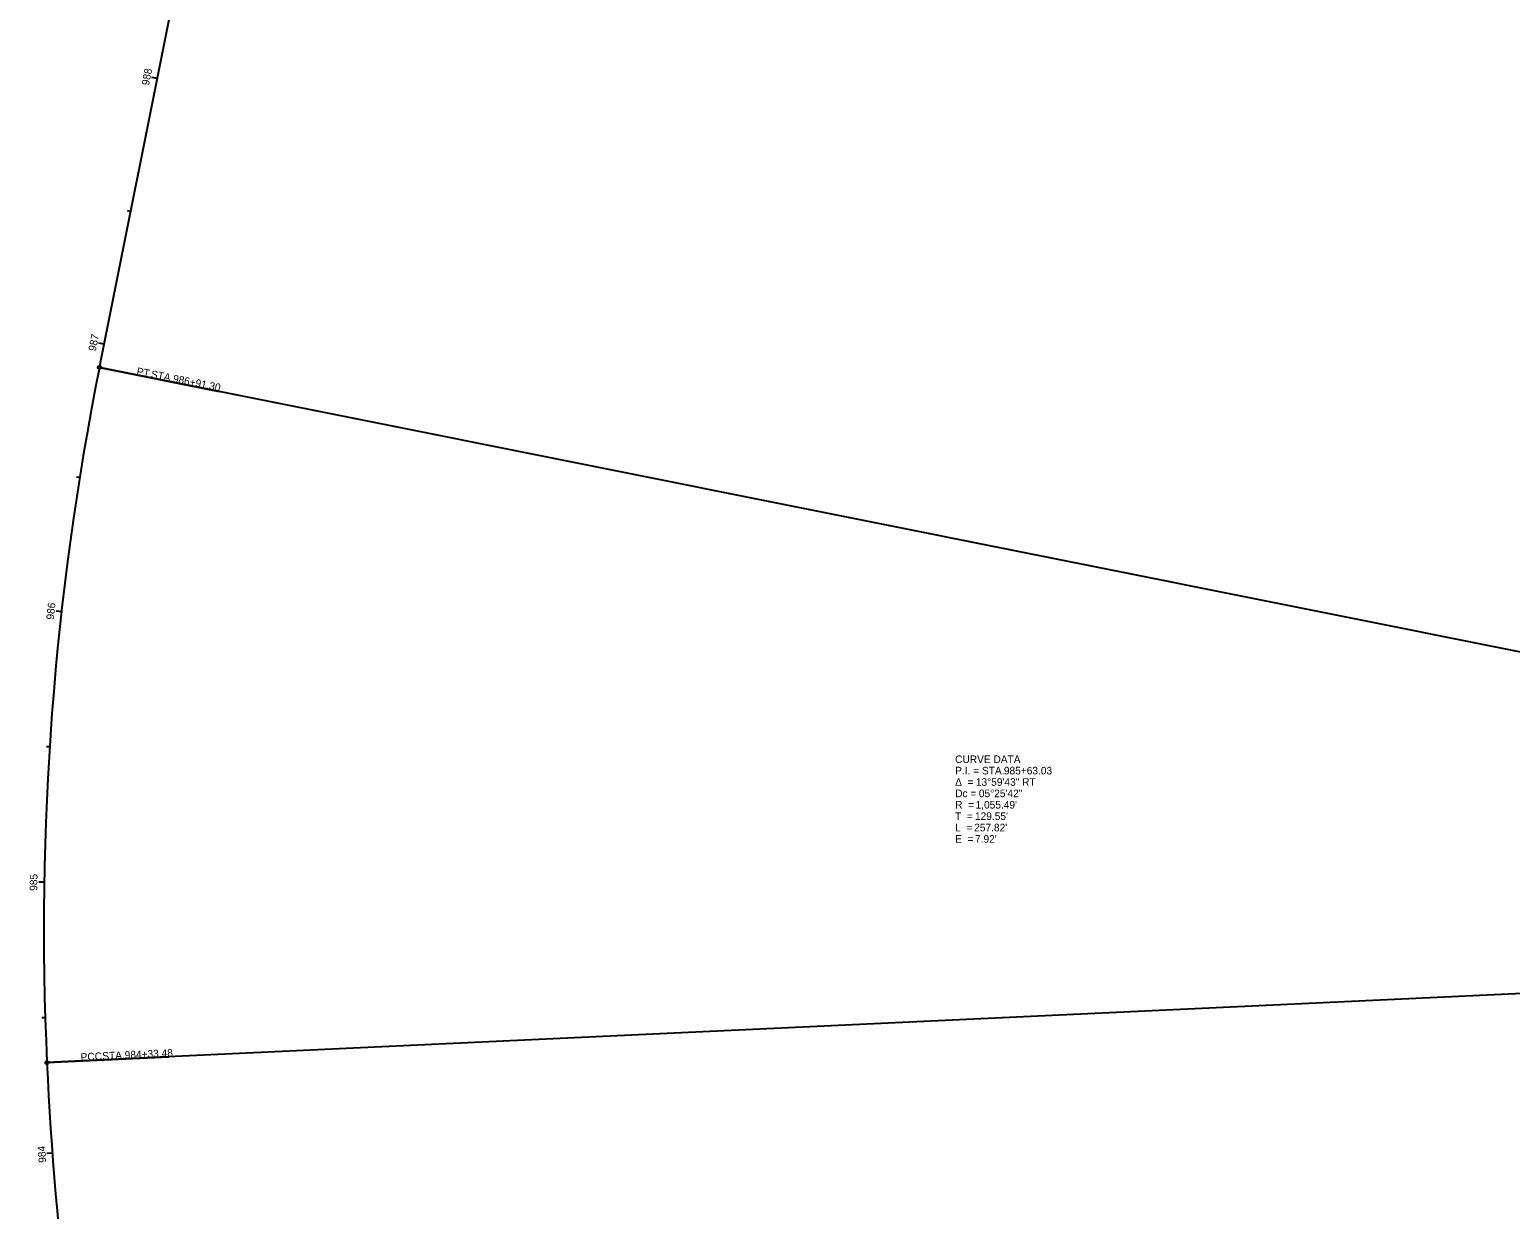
# Model space of a CAD drawing. Extents: x 2227316 to 2230534, y 679272 to 682221.
# Drawn here: x 2228257 to 2228803, y 680131 to 680566 of the extents above; entities that cross this region are included whole.
import ezdxf

# ---------------------------------------------------------------- set-up
doc = ezdxf.new("R2010")
doc.units = 0
for name, color, linetype in [('GE_X_Alignment', 7, 'Continuous'), ('GE_X_Alignment_100_Cardinal_Points', 7, 'Continuous'), ('GE_X_Alignment_100_Curve_Data', 7, 'Continuous'), ('GE_X_Alignment_100_Stations', 7, 'Continuous'), ('SC_Scratch1', 7, 'Continuous'), ('SC_Scratch2', 7, 'Continuous')]:
    doc.layers.add(name, color=color, linetype=linetype)

msp = doc.modelspace()

# ---------------------------------------------------------------- linework, layer by layer
at = {"layer": 'GE_X_Alignment'}
msp.add_line((2228282.37, 680441.81), (2228392.03, 680989.64), dxfattribs=at)
for centre, radius, start, end in [((2229317.33, 680234.63), 1055.49, 168.68003, 182.67534), ((2229522.92, 680244.24), 1261.31, 182.67534, 200.31734)]:
    msp.add_arc(centre, radius, start, end, dxfattribs=at)
at = {"layer": 'GE_X_Alignment_100_Cardinal_Points'}
for p, q in [((2228282.37, 680441.81), (2228326.49, 680432.98)), ((2228262.99, 680185.37), (2228307.94, 680187.47))]:
    msp.add_line(p, q, dxfattribs=at)
for centre in [(2228282.37, 680441.81), (2228262.99, 680185.37)]:
    msp.add_circle(centre, 0.6, dxfattribs=at)
at = {"layer": 'GE_X_Alignment_100_Stations'}
for p, q in [((2228303.71, 680548.4), (2228301.74, 680548.79)), ((2228293.89, 680499.37), (2228292.71, 680499.61)), ((2228284.08, 680450.35), (2228282.12, 680450.74)), ((2228275.06, 680401.17), (2228273.87, 680401.36)), ((2228268.34, 680351.63), (2228266.35, 680351.85)), ((2228263.98, 680301.82), (2228262.78, 680301.9)), ((2228261.98, 680251.87), (2228259.98, 680251.9)), ((2228262.34, 680201.88), (2228261.14, 680201.84)), ((2228264.99, 680151.95), (2228263, 680151.8))]:
    msp.add_line(p, q, dxfattribs=at)
at = {"layer": 'SC_Scratch1'}
msp.add_line((2228282.37, 680441.81), (2228392.03, 680989.64), dxfattribs=at)
for centre, radius, start, end in [((2229317.33, 680234.63), 1055.49, 168.68003, 182.67534), ((2229522.92, 680244.24), 1261.31, 182.67534, 200.31734)]:
    msp.add_arc(centre, radius, start, end, dxfattribs=at)
at = {"layer": 'SC_Scratch2'}
for p, q in [((2229317.33, 680234.63), (2228282.37, 680441.81)), ((2229522.92, 680244.24), (2228262.99, 680185.37))]:
    msp.add_line(p, q, dxfattribs=at)

# ---------------------------------------------------------------- texts
at = {"layer": 'GE_X_Alignment_100_Cardinal_Points'}
for s, rotation, p in [('PT', 348.68, (2228295.89, 680439.14)), (' STA. ', 348.68, (2228300.16, 680438.29)), ('986+91.30', 348.68, (2228309.3, 680436.46)), ('PCC', 2.6753, (2228275.47, 680185.99)), (' STA. ', 2.6753, (2228282.42, 680186.31)), ('984+33.48', 2.6753, (2228291.74, 680186.75))]:
    msp.add_text(s, height=2.8, rotation=rotation, dxfattribs=at).set_placement(p)
at = {"layer": 'GE_X_Alignment_100_Curve_Data'}
for s, p in [('CURVE DATA', (2228598.14, 680295.87)), ('P.I. = STA. ', (2228598.14, 680291.67)), ('985+63.03', (2228616.13, 680291.67)), ('Δ  = ', (2228598.14, 680287.47)), ('Dc = ', (2228598.14, 680283.27)), ('13°59\'43" RT', (2228605.79, 680287.47)), ('05°25\'42"', (2228606.89, 680283.27)), ('R  = ', (2228598.14, 680279.07)), ("1,055.49'", (2228605.68, 680279.07)), ('T  = ', (2228598.14, 680274.87)), ("129.55'", (2228605.46, 680274.87)), ('L  = ', (2228598.14, 680270.67)), ("257.82'", (2228605.18, 680270.67)), ('E  = ', (2228598.14, 680266.47)), ("7.92'", (2228605.48, 680266.47))]:
    msp.add_text(s, height=2.8, dxfattribs=at).set_placement(p)
at = {"layer": 'GE_X_Alignment_100_Stations'}
for s, rotation, p in [('988', 78.68, (2228300.62, 680545.71)), ('987', 78.68, (2228280.99, 680447.66)), ('986', 83.6359, (2228265.49, 680348.67)), ('985', 89.0643, (2228259.42, 680248.7)), ('984', 94.1961, (2228262.74, 680148.49))]:
    msp.add_text(s, height=2.8, rotation=rotation, dxfattribs=at).set_placement(p)

doc.saveas('drawing.dxf')
